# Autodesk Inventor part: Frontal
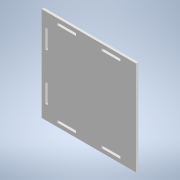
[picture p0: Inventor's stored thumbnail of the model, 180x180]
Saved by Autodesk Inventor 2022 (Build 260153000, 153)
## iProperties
Created: 2022-05
Part Number: Frontal
Material: Generic
Document SubType Name: Modeling
Designer: Daniel
Density: 1 g/cm^3
Appearance: Default
Author: Daniel
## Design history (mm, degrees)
extrude "Extrusion1" new body sketch "Sketch1" distance "d4" = 2.5; taper "d5" = 0 deg
sketch "Sketch2"
  geometry: L1 (65, 4)-(-35, 4) reference; L2 (65, 4)-(-35, -96); L3 (-28.5, -2.5)-(58.5, -2.5); L4 (58.5, -2.5)-(58.5, -89.5); L5 (58.5, -89.5)-(-28.5, -89.5); L6 (-28.5, -89.5)-(-28.5, -2.5); L7 (-28.5, -2.5)-(58.5, -89.5); L8 (58.5, -2.5)-(-28.5, -89.5); L9 (58.5, -2.5)-(15, -46); L10 (15, -46)-(58.5, -89.5); L11 (15, -46)-(-28.5, -89.5); L12 (-28.5, -2.5)-(15, -46); L13 (36.75, -24.25)-(33.214, -27.786); L14 (36.75, -67.75)-(33.214, -64.214); L15 (-6.75, -24.25)-(-3.214, -27.786); L16 (-6.75, -67.75)-(-3.214, -64.214); C1 r 6.5 at (33.214, -27.786); C2 r 6.5 at (33.214, -64.214); C3 r 6.5 at (-3.214, -27.786); C4 r 6.5 at (-3.214, -64.214); 1 further point
  constraints: 30 end point, 7 midpoint, 4 centre point, 4 coincident, 4 point on line, 2 collinear, 2 parallel, 1 horizontal, 1 perpendicular
  dimensions: "d6" = 87 distance of L4.end L5.end; "d7" = 87 distance of L3.end L4.end; "d8" = 5 distance of L13.start L13.end; "d9" = 5 distance of L14.start L14.end; "d10" = 5 distance of L15.start L15.end; "d11" = 5 distance of L16.start L16.end; "d12" = 13 diameter of C1; "d13" = 13 diameter of C2; "d14" = 13 diameter of C3; "d15" = 13 diameter of C4
extrude "Extrusion2" cut sketch "Sketch2" distance "d16" = 5 (= d10); taper "d17" = 0 deg
body "Solid1"
other parameters: "d0" = 87, "d1" = 87
